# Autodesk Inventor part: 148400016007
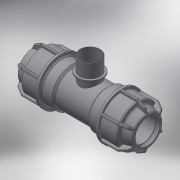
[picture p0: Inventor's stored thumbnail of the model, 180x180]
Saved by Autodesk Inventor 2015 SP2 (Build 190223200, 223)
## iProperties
Created: 2017-08
Part Number: 148400016007
Material: Generic
Description: PLASSON L.14 TEE MALE ADAPTOR (SILVER) 16-3/4"-16(20)
Document SubType Name: Modeling
Designer: KIM
Density: 1 g/cm^3
Appearance: Default
Author: KIM
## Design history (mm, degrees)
derived "148400.ipt"
feature "Solid1::148400.ipt"
feature "Solid2::148400.ipt"
tag "TaggingFeature1"
body "Solid1"
body "Solid2"
other parameters: "d1" = 16, "d2" = 44, "d4" = 15 deg, "d5" = 29.04, "d6" = 9.5832, "d10" = 42, "d16" = 16.32, "d17" = 2.2, "d22" = 25.6, "d24" = 2.2, "d25" = 37.8, "d26" = 31.5, "d27" = 2.2, "d28" = 135 deg, "d29" = 1.32, "d31" = 0.8, "d46" = 150 deg, "d49" = 2.1, "d50" = 0, "d58" = 0.48, "d61" = 360 deg, "d63" = 14.4, "d64" = 56.5, "d80" = 23.04, "d81" = 1.28, "d84" = 2.2, "d94" = 45, "d96" = 26.441, "d108" = 0.48, "d111" = 0, "d113" = 14.4, "d114" = 31.7292, "d115" = 18, "d116" = 1.8, "d117" = 21.1528, "d_" = 16, "R_" = 26.441, "E_" = 42, "H_" = 113, "l_" = 44, "l_2" = 18, "A_" = 45
